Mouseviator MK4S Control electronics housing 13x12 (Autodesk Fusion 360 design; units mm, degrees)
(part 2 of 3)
sketch "Sketch2" plane through (0, 61.9879, 0) normal (0, 1, 0) x axis (-1, 0, 0)
  line L1 (-11.0351, 74.95) -> (-130.8937, 74.95)
  line L2 (-130.8937, 74.95) -> (-130.8937, 5.05)
  line L3 (-11.0351, 74.95) -> (-11.0351, 5.05)
  line L4 (-11.0351, 5.05) -> (-130.8937, 5.05)
  line L5 (-11.0351, 74.95) -> (-11.0351, 5.05)
  line L6 (-130.8937, 74.95) -> (-11.0351, 74.95)
  line L7 (-130.8937, 5.05) -> (-130.8937, 74.95)
  line L8 (-120.8937, 64.95) -> (-21.0351, 64.95)
  line L9 (-120.8937, 15.05) -> (-120.8937, 64.95)
  line L10 (-21.0351, 15.05) -> (-120.8937, 15.05)
  line L11 (-21.0351, 64.95) -> (-21.0351, 15.05)
  circle C1 centre (-125.9644, 60) radius 1.7
  circle C2 centre (-125.9644, 20) radius 1.7
  circle C3 centre (-15.9644, 20) radius 1.7
  circle C4 centre (-15.9644, 60) radius 1.7
hole "Hole1" HoleDepth 4 HoleDiameter 3.4 TipAngle 118
extrude "Extrude2" cut sketch "Sketch2" profile of L8 L10 L9 L11 no distance stored
mirror_component "MirrorComponent3"
derived_instance "DerivedInstance3"
extrude "Extrude7" add sketch "left side holes" profile of C1 L13 L14 L15 L16 along normal blind 1.45 (= "( top_cover_thickness / 2 ) - wall_clearance")
extrude "Extrude3" cut sketch "base" profile of L9 L10 L11 L12 L13 L14 L15 L16 L17 L18 L19 L20 L21 L22 L23 L24 along normal blind 1.5 (= "top_cover_thickness / 2")
extrude "Extrude2" add sketch "Sketch1" along normal blind 2.5 (= "plate_thick / 2")
extrude "Extrude4" cut sketch "Sketch1" profile of L13 L12 L15 L14 L16 L17 C2 C3 C4 C5 along normal blind 2.55 (= "( plate_thick / 2 ) + wall_clearance")
sketch "Sketch1" plane through (0, 0, 0) normal (0, 0, 1) x axis (1, 0, 0)
  line L1 (-15, -9) -> (-15, 21)
  line L2 (-7, 6) -> (-28, 6)
  line L3 (-18, 16) -> (-18, 6)
  line L4 (-18, -4) -> (-18, 6)
  line L5 (-15, 21) -> (-18, 16)
  line L6 (-15, -9) -> (-18, -4)
  line L7 (-21, -9) -> (-18, -4)
  line L8 (-18, -4) -> (-18, 6)
  line L9 (-18, 16) -> (-18, 6)
  line L10 (-21, 21) -> (-18, 16)
  line L11 (-21, -9) -> (-21, 21)
  line L12 (-15.05, 20.8195) -> (-18, 15.9028)
  line L13 (-15.05, -8.8195) -> (-15.05, 20.8195)
  line L14 (-15.05, -8.8195) -> (-18, -3.9028)
  line L15 (-20.95, -8.8195) -> (-18, -3.9028)
  line L16 (-20.95, -8.8195) -> (-20.95, 20.8195)
  line L17 (-20.95, 20.8195) -> (-18, 15.9028)
  line L18 (-16.5, -15) -> (-16.5, 22.7414)
  circle C1 centre (-16.5, 11) radius 0.75
  circle C2 centre (-16.5, 11) radius 0.7
  circle C3 centre (-16.5, 1) radius 0.7
  circle C4 centre (-19.5, 11) radius 0.7
  circle C5 centre (-19.5, 1) radius 0.7
  point P2 (-15, 21)
  point P13 (-21, 21)
  point P3 (-15, -9)
  point P10 (-21, -9)
  point P6 (-18, 6)
  point P11 (-18, 6)
  point P7 (-18, 16)
  point P12 (-18, 16)
  point P8 (-18, -4)
  point P9 (-18, -4)
  point P22 (-16.5, 11)
  vertical L1
  horizontal L2
  perpendicular L2 L3
  perpendicular L2 L4
  symmetric P2 L3 P13
  symmetric P3 L3 P10
  symmetric P6 L3 P11
  symmetric P7 L3 P12
  symmetric L3 P8 P9
  parallel L1 L18
  coincident L18 P22
  symmetric L2 C2 C3
  symmetric L4 C2 C4
  symmetric L4 C3 C5
  dimension "d49_1" distance P6 P7 = 10 (= "join_width1")
  dimension "d50_1" distance P6 P8 = 10 (= "join_width1")
  dimension "d51_1" distance P2 P3 = 30 (= "join_width2 * 2")
  dimension "d52_1" distance L1 L3 = 3 (= "join_depth")
  dimension "joiner_spacing_3" = -0.05
  dimension "d256_1" distance L9 L18 = 1.5 (= "join_depth / 2")
  dimension "d257_1" diameter C1 = 1.5 (= "join_key_d")
  dimension "d258_1" distance L2 P22 = 5 (= "join_key_distance")
extrude "Extrude1" new body sketch "Sketch1" profile of L13 L12 L15 L14 L16 L17 along normal blind 5 (= "plate_thick") named "d54_1"
extrude "Extrude4" cut sketch "Sketch1" profile of L13 L12 L15 L14 L16 L17 C2 C3 C4 C5 along normal blind 2.55 (= "( plate_thick / 2 ) + wall_clearance") named "d260_1"
sketch "Sketch1" plane through (0, 0, 0) normal (0, 0, 1) x axis (1, 0, 0)
  line L1 (-15, -9) -> (-15, 21)
  line L2 (-7, 6) -> (-28, 6)
  line L3 (-18, 16) -> (-18, 6)
  line L4 (-18, -4) -> (-18, 6)
  line L5 (-15, 21) -> (-18, 16)
  line L6 (-15, -9) -> (-18, -4)
  line L7 (-18, -4) -> (-18, 6)
  line L8 (-18, 16) -> (-18, 6)
  line L9 (-15.05, 20.8195) -> (-18, 15.9028)
  line L10 (-15.05, -8.8195) -> (-15.05, 20.8195)
  line L11 (-15.05, -8.8195) -> (-18, -3.9028)
  line L12 (-16.5, -15) -> (-16.5, 22.7414)
  circle C1 centre (-16.5, 11) radius 0.75
  circle C2 centre (-16.5, 11) radius 0.7
  circle C3 centre (-16.5, 1) radius 0.7
  point P6 (-18, 6)
  point P10 (-18, 6)
  point P7 (-18, 16)
  point P11 (-18, 16)
  point P8 (-18, -4)
  point P9 (-18, -4)
  point P17 (-16.5, 11)
  point P2 (-15, 21)
  point P3 (-15, -9)
  vertical L1
  horizontal L2
  perpendicular L2 L3
  perpendicular L2 L4
  symmetric P6 L3 P10
  symmetric P7 L3 P11
  symmetric L3 P8 P9
  parallel L1 L12
  coincident L12 P17
  symmetric L2 C2 C3
  dimension "d49_1_2" distance P6 P7 = 10 (= "join_width1")
  dimension "d50_1_2" distance P6 P8 = 10 (= "join_width1")
  dimension "d51_1_2" distance P2 P3 = 30 (= "join_width2 * 2")
  dimension "d52_1_2" distance L1 L3 = 3 (= "join_depth")
  dimension "joiner_spacing_3_2" = -0.05
  dimension "d256_1_2" distance L8 L12 = 1.5 (= "join_depth / 2")
  dimension "d257_1_2" diameter C1 = 1.5 (= "join_key_d")
  dimension "d258_1_2" distance L2 P17 = 5 (= "join_key_distance")
position "Position3"
extrude "Extrude5" new body sketch "Sketch1" profile of L3 L7 L10 L9 L11 C2 C3 along normal blind 5 (= "plate_thick")
extrude "Extrude6" cut sketch "Sketch1" profile of L3 L7 L10 L9 L11 C2 C3 along normal blind 2.55 (= "( plate_thick / 2 ) + wall_clearance")
sketch "Sketch1" plane through (0, 0, 5) normal (0, 0, 1) x axis (-1, 0, 0)
  line L1 (-128.9644, -53.9879) -> (-128.9644, -59.9879)
  line L2 (-122.9644, -53.9879) -> (-128.9644, -53.9879)
  line L3 (-122.9644, -59.9879) -> (-122.9644, -53.9879)
  line L4 (-128.9644, -59.9879) -> (-122.9644, -59.9879)
  line L5 (-12.9644, 60.0121) -> (-12.9644, 66.0121)
  line L6 (-18.9644, 60.0121) -> (-12.9644, 60.0121)
  line L7 (-18.9644, 66.0121) -> (-18.9644, 60.0121)
  line L8 (-12.9644, 66.0121) -> (-18.9644, 66.0121)
  line L9 (-60.9644, -51.9879) -> (-20.9644, -51.9879)
  line L10 (-55.9644, -54.9879) -> (-60.9644, -51.9879)
  line L11 (-85.9644, -54.9879) -> (-55.9644, -54.9879)
  line L12 (-80.9644, -51.9879) -> (-85.9644, -54.9879)
  line L13 (-120.9644, -51.9879) -> (-80.9644, -51.9879)
  line L14 (-120.9644, -6.9879) -> (-120.9644, -51.9879)
  line L15 (-123.9644, -11.9879) -> (-120.9644, -6.9879)
  line L16 (-123.9644, 18.0121) -> (-123.9644, -11.9879)
  line L17 (-120.9644, 13.0121) -> (-123.9644, 18.0121)
  line L18 (-120.9644, 58.0121) -> (-120.9644, 13.0121)
  line L19 (-80.9644, 58.0121) -> (-120.9644, 58.0121)
  line L20 (-85.9644, 61.0121) -> (-80.9644, 58.0121)
  line L21 (-55.9644, 61.0121) -> (-85.9644, 61.0121)
  line L22 (-60.9644, 58.0121) -> (-55.9644, 61.0121)
  line L23 (-20.9644, 58.0121) -> (-60.9644, 58.0121)
  line L24 (-20.9644, 13.0121) -> (-20.9644, 58.0121)
  line L25 (-17.9644, 18.0121) -> (-20.9644, 13.0121)
  line L26 (-17.9644, -11.9879) -> (-17.9644, 18.0121)
  line L27 (-20.9644, -6.9879) -> (-17.9644, -11.9879)
  line L28 (-20.9644, -51.9879) -> (-20.9644, -6.9879)
  line L29 (-12.9644, -53.9879) -> (-18.9644, -53.9879)
  line L30 (-12.9644, -59.9879) -> (-12.9644, -53.9879)
  line L31 (-18.9644, -59.9879) -> (-12.9644, -59.9879)
  line L32 (-18.9644, -53.9879) -> (-18.9644, -59.9879)
  line L33 (-128.9644, 60.0121) -> (-122.9644, 60.0121)
  line L34 (-128.9644, 66.0121) -> (-128.9644, 60.0121)
  line L35 (-122.9644, 66.0121) -> (-128.9644, 66.0121)
  line L36 (-122.9644, 60.0121) -> (-122.9644, 66.0121)
  line L37 (-10.9644, -6.9879) -> (-10.9644, -61.9879)
  line L38 (-13.9644, -11.9879) -> (-10.9644, -6.9879)
  line L39 (-13.9644, 18.0121) -> (-13.9644, -11.9879)
  line L40 (-10.9644, 13.0121) -> (-13.9644, 18.0121)
  line L41 (-10.9644, 68.0121) -> (-10.9644, 13.0121)
  line L42 (-60.9644, 68.0121) -> (-10.9644, 68.0121)
  line L43 (-55.9644, 65.0121) -> (-60.9644, 68.0121)
  line L44 (-85.9644, 65.0121) -> (-55.9644, 65.0121)
  line L45 (-80.9644, 68.0121) -> (-85.9644, 65.0121)
  line L46 (-130.9644, 68.0121) -> (-80.9644, 68.0121)
  line L47 (-130.9644, 13.0121) -> (-130.9644, 68.0121)
  line L48 (-127.9644, 18.0121) -> (-130.9644, 13.0121)
  line L49 (-127.9644, -11.9879) -> (-127.9644, 18.0121)
  line L50 (-130.9644, -6.9879) -> (-127.9644, -11.9879)
  line L51 (-130.9644, -61.9879) -> (-130.9644, -6.9879)
  line L52 (-80.9644, -61.9879) -> (-130.9644, -61.9879)
  line L53 (-85.9644, -58.9879) -> (-80.9644, -61.9879)
  line L54 (-55.9644, -58.9879) -> (-85.9644, -58.9879)
  line L55 (-60.9644, -61.9879) -> (-55.9644, -58.9879)
  line L56 (-10.9644, -61.9879) -> (-60.9644, -61.9879)
  line L57 (-130.9644, -61.9879) -> (-10.9644, -61.9879)
  line L58 (-129.9644, -60.9879) -> (-130.9644, -61.9879)
  line L59 (-121.9644, -60.9879) -> (-129.9644, -60.9879)
  line L60 (-121.9644, -59.9879) -> (-121.9644, -60.9879)
  line L61 (-19.9644, -59.9879) -> (-121.9644, -59.9879)
  line L62 (-19.9644, -60.9879) -> (-19.9644, -59.9879)
  line L63 (-11.9644, -60.9879) -> (-19.9644, -60.9879)
  line L64 (-10.9644, -61.9879) -> (-11.9644, -60.9879)
  line L65 (-129.9437, -61.0379) -> (-130.8937, -61.9879)
  line L66 (-121.9144, -61.0379) -> (-129.9437, -61.0379)
  line L67 (-121.9144, -60.0379) -> (-121.9144, -61.0379)
  line L68 (-20.0144, -60.0379) -> (-121.9144, -60.0379)
  line L69 (-20.0144, -61.0379) -> (-20.0144, -60.0379)
  line L70 (-11.9851, -61.0379) -> (-20.0144, -61.0379)
  line L71 (-11.0351, -61.9879) -> (-11.9851, -61.0379)
  circle C1 centre (-24.4644, 61.5121) radius 1.7
  circle C2 centre (-123.9644, 54.5121) radius 1.7
  circle C3 centre (-117.4644, -55.4879) radius 1.7
  circle C4 centre (-17.4644, -48.4879) radius 1.7
  circle C5 centre (-24.4644, -55.4879) radius 1.7
  circle C6 centre (-123.9644, -48.4879) radius 1.7
  circle C7 centre (-117.4644, 61.5121) radius 1.7
  circle C8 centre (-17.4644, 54.5121) radius 1.7
  point P46 (-10.9644, -61.9879)
  point P74 (-10.9644, -61.9879)
  point P61 (-130.9644, -61.9879)
  point P76 (-130.9644, -61.9879)
  point P68 (-129.9644, -60.9879)
  point P77 (-129.9644, -60.9879)
  point P69 (-121.9644, -60.9879)
  point P78 (-121.9644, -60.9879)
  point P70 (-121.9644, -59.9879)
  point P79 (-121.9644, -59.9879)
  point P71 (-19.9644, -59.9879)
  point P80 (-19.9644, -59.9879)
  point P72 (-19.9644, -60.9879)
  point P81 (-19.9644, -60.9879)
  point P73 (-11.9644, -60.9879)
  point P82 (-11.9644, -60.9879)
  point P89 (-11.0351, -61.9879)
  point P90 (-130.8937, -61.9879)
  point P75 (-130.9644, -61.9879)
  coincident P46 P74
  coincident P61 P76
  coincident P68 P77
  coincident P69 P78
  coincident P70 P79
  coincident P71 P80
  coincident P72 P81
  coincident P73 P82
  coincident L56 P89
  coincident L52 P90
  dimension "d228_1" distance L57 L70 = 0.95 (= "side_wall_thick1")
  dimension "d229_1" distance L57 L68 = 1.95 (= "side_wall_thick2")
  dimension "d230_1" distance L57 L66 = 0.95 (= "side_wall_thick1")
  dimension "d231_1" distance P74 P75 = 120 (= "plate_height")
  dimension "d232_1" distance L64 L71 = 0.05 (= "wall_clearance")
  dimension "d233_1" distance L58 L65 = 0.05 (= "wall_clearance")
  dimension "d234_1" angle L57 L58 = 45 (= "wall_rorner_angle")
  dimension "d235_1" distance P74 L69 = 9.05 (= "side_wall_col_length")
  dimension "d244_1" distance P75 L67 = 9.05 (= "side_wall_col_length")
extrude "Extrude1" new body sketch "Sketch1" profile of L52 L53 L55 L56 blind 69.9 (= "column_height - ( 2 * wall_clearance )") named "d217_1" from offset 0.05 (= "wall_clearance") named "d216_1"
sketch "Sketch2" plane through (0, 61.9879, 0) normal (0, 1, 0) x axis (-1, 0, 0)
  line L1 (-11.0351, 74.95) -> (-130.8937, 74.95)
  line L2 (-130.8937, 74.95) -> (-130.8937, 5.05)
  line L3 (-11.0351, 74.95) -> (-11.0351, 5.05)
  line L4 (-11.0351, 5.05) -> (-130.8937, 5.05)
  line L5 (-11.0351, 74.95) -> (-11.0351, 5.05)
  line L6 (-130.8937, 74.95) -> (-11.0351, 74.95)
  line L7 (-130.8937, 5.05) -> (-130.8937, 74.95)
  line L8 (-120.8937, 64.95) -> (-21.0351, 64.95)
  line L9 (-120.8937, 15.05) -> (-120.8937, 64.95)
  line L10 (-21.0351, 15.05) -> (-120.8937, 15.05)
  line L11 (-21.0351, 64.95) -> (-21.0351, 15.05)
  circle C1 centre (-125.9644, 60) radius 1.7
  circle C2 centre (-125.9644, 20) radius 1.7
  circle C3 centre (-15.9644, 20) radius 1.7
  circle C4 centre (-15.9644, 60) radius 1.7
hole "Hole1" HoleDepth 4 named "d220_1" HoleDiameter 3.4 named "d221_1" TipAngle 118 named "d222_1"
sketch "Sketch3" plane through (0, 61.9879, 0) normal (0, 1, 0) x axis (-1, 0, 0)
  line L1 (-37.0714, 20.7092) -> (-37, 5)
  line L2 (-27.0715, 20.7546) -> (-27, 5)
  line L3 (-130.8937, 5.05) -> (-130.8937, 74.95)
  line L4 (-11.0351, 5.05) -> (-130.8937, 5.05)
  line L5 (-11.0351, 74.95) -> (-11.0351, 5.05)
  line L6 (-130.8937, 74.95) -> (-11.0351, 74.95)
  arc A1 centre (-32.0715, 20.7319) radius 5 clockwise from (-37.0714, 20.7092) to (-27.0715, 20.7546)
  tangent L1 A1
  tangent L2 A1
  dimension "d338" diameter A1 = 10
extrude "Extrude3" cut sketch "Sketch3" profile of A1 L1 L2 L4 no distance stored
sketch "Sketch1" plane through (0, 0, 5) normal (0, 0, 1) x axis (-1, 0, 0)
  line L1 (-128.9644, -53.9879) -> (-128.9644, -59.9879)
  line L2 (-122.9644, -53.9879) -> (-128.9644, -53.9879)
  line L3 (-122.9644, -59.9879) -> (-122.9644, -53.9879)
  line L4 (-128.9644, -59.9879) -> (-122.9644, -59.9879)
  line L5 (-12.9644, 60.0121) -> (-12.9644, 66.0121)
  line L6 (-18.9644, 60.0121) -> (-12.9644, 60.0121)
  line L7 (-18.9644, 66.0121) -> (-18.9644, 60.0121)
  line L8 (-12.9644, 66.0121) -> (-18.9644, 66.0121)
  line L9 (-60.9644, -51.9879) -> (-20.9644, -51.9879)
  line L10 (-55.9644, -54.9879) -> (-60.9644, -51.9879)
  line L11 (-85.9644, -54.9879) -> (-55.9644, -54.9879)
  line L12 (-80.9644, -51.9879) -> (-85.9644, -54.9879)
  line L13 (-120.9644, -51.9879) -> (-80.9644, -51.9879)
  line L14 (-120.9644, -6.9879) -> (-120.9644, -51.9879)
  line L15 (-123.9644, -11.9879) -> (-120.9644, -6.9879)
  line L16 (-123.9644, 18.0121) -> (-123.9644, -11.9879)
  line L17 (-120.9644, 13.0121) -> (-123.9644, 18.0121)
  line L18 (-120.9644, 58.0121) -> (-120.9644, 13.0121)
  line L19 (-80.9644, 58.0121) -> (-120.9644, 58.0121)
  line L20 (-85.9644, 61.0121) -> (-80.9644, 58.0121)
  line L21 (-55.9644, 61.0121) -> (-85.9644, 61.0121)
  line L22 (-60.9644, 58.0121) -> (-55.9644, 61.0121)
  line L23 (-20.9644, 58.0121) -> (-60.9644, 58.0121)
  line L24 (-20.9644, 13.0121) -> (-20.9644, 58.0121)
  line L25 (-17.9644, 18.0121) -> (-20.9644, 13.0121)
  line L26 (-17.9644, -11.9879) -> (-17.9644, 18.0121)
  line L27 (-20.9644, -6.9879) -> (-17.9644, -11.9879)
  line L28 (-20.9644, -51.9879) -> (-20.9644, -6.9879)
  line L29 (-12.9644, -53.9879) -> (-18.9644, -53.9879)
  line L30 (-12.9644, -59.9879) -> (-12.9644, -53.9879)
  line L31 (-18.9644, -59.9879) -> (-12.9644, -59.9879)
  line L32 (-18.9644, -53.9879) -> (-18.9644, -59.9879)
  line L33 (-128.9644, 60.0121) -> (-122.9644, 60.0121)
  line L34 (-128.9644, 66.0121) -> (-128.9644, 60.0121)
  line L35 (-122.9644, 66.0121) -> (-128.9644, 66.0121)
  line L36 (-122.9644, 60.0121) -> (-122.9644, 66.0121)
  line L37 (-10.9644, -6.9879) -> (-10.9644, -61.9879)
  line L38 (-13.9644, -11.9879) -> (-10.9644, -6.9879)
  line L39 (-13.9644, 18.0121) -> (-13.9644, -11.9879)
  line L40 (-10.9644, 13.0121) -> (-13.9644, 18.0121)
  line L41 (-10.9644, 68.0121) -> (-10.9644, 13.0121)
  line L42 (-60.9644, 68.0121) -> (-10.9644, 68.0121)
  line L43 (-55.9644, 65.0121) -> (-60.9644, 68.0121)
  line L44 (-85.9644, 65.0121) -> (-55.9644, 65.0121)
  line L45 (-80.9644, 68.0121) -> (-85.9644, 65.0121)
  line L46 (-130.9644, 68.0121) -> (-80.9644, 68.0121)
  line L47 (-130.9644, 13.0121) -> (-130.9644, 68.0121)
  line L48 (-127.9644, 18.0121) -> (-130.9644, 13.0121)
  line L49 (-127.9644, -11.9879) -> (-127.9644, 18.0121)
  line L50 (-130.9644, -6.9879) -> (-127.9644, -11.9879)
  line L51 (-130.9644, -61.9879) -> (-130.9644, -6.9879)
  line L52 (-80.9644, -61.9879) -> (-130.9644, -61.9879)
  line L53 (-85.9644, -58.9879) -> (-80.9644, -61.9879)
  line L54 (-55.9644, -58.9879) -> (-85.9644, -58.9879)
  line L55 (-60.9644, -61.9879) -> (-55.9644, -58.9879)
  line L56 (-10.9644, -61.9879) -> (-60.9644, -61.9879)
  line L57 (-130.9644, -61.9879) -> (-10.9644, -61.9879)
  line L58 (-129.9644, -60.9879) -> (-130.9644, -61.9879)
  line L59 (-121.9644, -60.9879) -> (-129.9644, -60.9879)
  line L60 (-121.9644, -59.9879) -> (-121.9644, -60.9879)
  line L61 (-19.9644, -59.9879) -> (-121.9644, -59.9879)
  line L62 (-19.9644, -60.9879) -> (-19.9644, -59.9879)
  line L63 (-11.9644, -60.9879) -> (-19.9644, -60.9879)
  line L64 (-10.9644, -61.9879) -> (-11.9644, -60.9879)
  line L65 (-129.9437, -61.0379) -> (-130.8937, -61.9879)
  line L66 (-121.9144, -61.0379) -> (-129.9437, -61.0379)
  line L67 (-121.9144, -60.0379) -> (-121.9144, -61.0379)
  line L68 (-20.0144, -60.0379) -> (-121.9144, -60.0379)
  line L69 (-20.0144, -61.0379) -> (-20.0144, -60.0379)
  line L70 (-11.9851, -61.0379) -> (-20.0144, -61.0379)
  line L71 (-11.0351, -61.9879) -> (-11.9851, -61.0379)
  circle C1 centre (-24.4644, 61.5121) radius 1.7
  circle C2 centre (-123.9644, 54.5121) radius 1.7
  circle C3 centre (-117.4644, -55.4879) radius 1.7
  circle C4 centre (-17.4644, -48.4879) radius 1.7
  circle C5 centre (-24.4644, -55.4879) radius 1.7
  circle C6 centre (-123.9644, -48.4879) radius 1.7
  circle C7 centre (-117.4644, 61.5121) radius 1.7
  circle C8 centre (-17.4644, 54.5121) radius 1.7
  point P46 (-10.9644, -61.9879)
  point P74 (-10.9644, -61.9879)
  point P61 (-130.9644, -61.9879)
  point P76 (-130.9644, -61.9879)
  point P68 (-129.9644, -60.9879)
  point P77 (-129.9644, -60.9879)
  point P69 (-121.9644, -60.9879)
  point P78 (-121.9644, -60.9879)
  point P70 (-121.9644, -59.9879)
  point P79 (-121.9644, -59.9879)
  point P71 (-19.9644, -59.9879)
  point P80 (-19.9644, -59.9879)
  point P72 (-19.9644, -60.9879)
  point P81 (-19.9644, -60.9879)
  point P73 (-11.9644, -60.9879)
  point P82 (-11.9644, -60.9879)
  point P89 (-11.0351, -61.9879)
  point P90 (-130.8937, -61.9879)
  point P75 (-130.9644, -61.9879)
  coincident P46 P74
  coincident P61 P76
  coincident P68 P77
  coincident P69 P78
  coincident P70 P79
  coincident P71 P80
  coincident P72 P81
  coincident P73 P82
  coincident L56 P89
  coincident L52 P90
  dimension "d228_2" distance L57 L70 = 0.95 (= "side_wall_thick1")
  dimension "d229_2" distance L57 L68 = 1.95 (= "side_wall_thick2")
  dimension "d230_2" distance L57 L66 = 0.95 (= "side_wall_thick1")
  dimension "d231_2" distance P74 P75 = 120 (= "plate_height")
  dimension "d232_2" distance L64 L71 = 0.05 (= "wall_clearance")
  dimension "d233_2" distance L58 L65 = 0.05 (= "wall_clearance")
  dimension "d234_2" angle L57 L58 = 45 (= "wall_rorner_angle")
  dimension "d235_2" distance P74 L69 = 9.05 (= "side_wall_col_length")
  dimension "d244_2" distance P75 L67 = 9.05 (= "side_wall_col_length")
extrude "Extrude1" new body sketch "Sketch1" profile of L52 L53 L55 L56 blind 69.9 (= "column_height - ( 2 * wall_clearance )") named "d217_2" from offset 0.05 (= "wall_clearance") named "d216_2"
sketch "Sketch2" plane through (0, 61.9879, 0) normal (0, 1, 0) x axis (-1, 0, 0)
  line L1 (-11.0351, 74.95) -> (-130.8937, 74.95)
  line L2 (-130.8937, 74.95) -> (-130.8937, 5.05)
  line L3 (-11.0351, 74.95) -> (-11.0351, 5.05)
  line L4 (-11.0351, 5.05) -> (-130.8937, 5.05)
  line L5 (-11.0351, 74.95) -> (-11.0351, 5.05)
  line L6 (-130.8937, 74.95) -> (-11.0351, 74.95)
  line L7 (-130.8937, 5.05) -> (-130.8937, 74.95)
  line L8 (-120.8937, 64.95) -> (-21.0351, 64.95)
  line L9 (-120.8937, 15.05) -> (-120.8937, 64.95)
  line L10 (-21.0351, 15.05) -> (-120.8937, 15.05)
  line L11 (-21.0351, 64.95) -> (-21.0351, 15.05)
  circle C1 centre (-125.9644, 60) radius 1.7
  circle C2 centre (-125.9644, 20) radius 1.7
  circle C3 centre (-15.9644, 20) radius 1.7
  circle C4 centre (-15.9644, 60) radius 1.7
hole "Hole1" HoleDepth 4 named "d220_2" HoleDiameter 3.4 named "d221_2" TipAngle 118 named "d222_2"
sketch "wall_base" plane through (0, 0, 5) normal (0, 0, 1) x axis (-1, 0, 0)
  line L1 (-128.9644, -53.9879) -> (-128.9644, -59.9879)
  line L2 (-122.9644, -53.9879) -> (-128.9644, -53.9879)
  line L3 (-122.9644, -59.9879) -> (-122.9644, -53.9879)
  line L4 (-128.9644, -59.9879) -> (-122.9644, -59.9879)
  line L5 (-12.9644, 60.0121) -> (-12.9644, 66.0121)
  line L6 (-18.9644, 60.0121) -> (-12.9644, 60.0121)
  line L7 (-18.9644, 66.0121) -> (-18.9644, 60.0121)
  line L8 (-12.9644, 66.0121) -> (-18.9644, 66.0121)
  line L9 (-60.9644, -51.9879) -> (-20.9644, -51.9879)
  line L10 (-55.9644, -54.9879) -> (-60.9644, -51.9879)
  line L11 (-85.9644, -54.9879) -> (-55.9644, -54.9879)
  line L12 (-80.9644, -51.9879) -> (-85.9644, -54.9879)
  line L13 (-120.9644, -51.9879) -> (-80.9644, -51.9879)
  line L14 (-120.9644, -6.9879) -> (-120.9644, -51.9879)
  line L15 (-123.9644, -11.9879) -> (-120.9644, -6.9879)
  line L16 (-123.9644, 18.0121) -> (-123.9644, -11.9879)
  line L17 (-120.9644, 13.0121) -> (-123.9644, 18.0121)
  line L18 (-120.9644, 58.0121) -> (-120.9644, 13.0121)
  line L19 (-80.9644, 58.0121) -> (-120.9644, 58.0121)
  line L20 (-85.9644, 61.0121) -> (-80.9644, 58.0121)
  line L21 (-55.9644, 61.0121) -> (-85.9644, 61.0121)
  line L22 (-60.9644, 58.0121) -> (-55.9644, 61.0121)
  line L23 (-20.9644, 58.0121) -> (-60.9644, 58.0121)
  line L24 (-20.9644, 13.0121) -> (-20.9644, 58.0121)
  line L25 (-17.9644, 18.0121) -> (-20.9644, 13.0121)
  line L26 (-17.9644, -11.9879) -> (-17.9644, 18.0121)
  line L27 (-20.9644, -6.9879) -> (-17.9644, -11.9879)
  line L28 (-20.9644, -51.9879) -> (-20.9644, -6.9879)
  line L29 (-12.9644, -53.9879) -> (-18.9644, -53.9879)
  line L30 (-12.9644, -59.9879) -> (-12.9644, -53.9879)
  line L31 (-18.9644, -59.9879) -> (-12.9644, -59.9879)
  line L32 (-18.9644, -53.9879) -> (-18.9644, -59.9879)
  line L33 (-128.9644, 60.0121) -> (-122.9644, 60.0121)
  line L34 (-128.9644, 66.0121) -> (-128.9644, 60.0121)
  line L35 (-122.9644, 66.0121) -> (-128.9644, 66.0121)
  line L36 (-122.9644, 60.0121) -> (-122.9644, 66.0121)
  line L37 (-10.9644, -6.9879) -> (-10.9644, -61.9879)
  line L38 (-13.9644, -11.9879) -> (-10.9644, -6.9879)
  line L39 (-13.9644, 18.0121) -> (-13.9644, -11.9879)
  line L40 (-10.9644, 13.0121) -> (-13.9644, 18.0121)
  line L41 (-10.9644, 68.0121) -> (-10.9644, 13.0121)
  line L42 (-60.9644, 68.0121) -> (-10.9644, 68.0121)
  line L43 (-55.9644, 65.0121) -> (-60.9644, 68.0121)
  line L44 (-85.9644, 65.0121) -> (-55.9644, 65.0121)
  line L45 (-80.9644, 68.0121) -> (-85.9644, 65.0121)
  line L46 (-130.9644, 68.0121) -> (-80.9644, 68.0121)
  line L47 (-130.9644, 13.0121) -> (-130.9644, 68.0121)
  line L48 (-127.9644, 18.0121) -> (-130.9644, 13.0121)
  line L49 (-127.9644, -11.9879) -> (-127.9644, 18.0121)
  line L50 (-130.9644, -6.9879) -> (-127.9644, -11.9879)
  line L51 (-130.9644, -61.9879) -> (-130.9644, -6.9879)
  line L52 (-80.9644, -61.9879) -> (-130.9644, -61.9879)
  line L53 (-85.9644, -58.9879) -> (-80.9644, -61.9879)
  line L54 (-55.9644, -58.9879) -> (-85.9644, -58.9879)
  line L55 (-60.9644, -61.9879) -> (-55.9644, -58.9879)
  line L56 (-10.9644, -61.9879) -> (-60.9644, -61.9879)
  line L57 (-130.9644, -61.9879) -> (-130.9644, 68.0121)
  line L58 (-130.9644, -61.9172) -> (-130.0144, -60.9672)
  line L59 (-130.0144, -52.9379) -> (-130.0144, -60.9672)
  line L60 (-129.0144, -52.9379) -> (-130.0144, -52.9379)
  line L61 (-129.0144, 58.9451) -> (-129.0144, -52.9379)
  line L62 (-130.0144, 58.9621) -> (-129.0144, 58.9451)
  line L63 (-130.0144, 66.9914) -> (-130.0144, 58.9621)
  line L64 (-130.9644, 67.9414) -> (-130.0144, 66.9914)
  line L65 (-129.9644, -52.9879) -> (-129.9644, -60.9879)
  line L66 (-128.9644, -52.9879) -> (-129.9644, -52.9879)
  line L67 (-128.9644, 58.9942) -> (-128.9644, -52.9879)
  line L68 (-129.9644, 59.0113) -> (-128.9644, 58.9942)
  line L69 (-129.9644, 67.0121) -> (-129.9644, 59.0113)
  line L70 (-130.9644, -61.9879) -> (-129.9644, -60.9879)
  line L71 (-130.9644, 68.0121) -> (-129.9644, 67.0121)
  circle C1 centre (-24.4644, 61.5121) radius 1.7
  circle C2 centre (-123.9644, 54.5121) radius 1.7
  circle C3 centre (-117.4644, -55.4879) radius 1.7
  circle C4 centre (-17.4644, -48.4879) radius 1.7
  circle C5 centre (-24.4644, -55.4879) radius 1.7
  circle C6 centre (-123.9644, -48.4879) radius 1.7
  circle C7 centre (-117.4644, 61.5121) radius 1.7
  circle C8 centre (-17.4644, 54.5121) radius 1.7
  point P69 (-130.9644, 68.0121)
  point P74 (-130.9644, 68.0121)
  point P68 (-130.9644, -61.9879)
  point P75 (-130.9644, -61.9879)
  point P82 (-130.9644, 67.9414)
  point P83 (-130.9644, -61.9172)
  point P90 (-130.9644, -61.9879)
  point P91 (-130.9644, 68.0121)
  point P77 (-130.0144, -52.9379)
  point P80 (-130.0144, 58.9621)
  coincident P69 P74
  coincident P68 P75
  coincident L47 P82
  coincident L51 P83
  coincident P68 P90
  parallel L58 L70
  coincident P69 P91
  dimension "d147_1" distance L57 L63 = 0.95 (= "side_wall_thick1")
  dimension "d148_1" distance L57 L61 = 1.95 (= "side_wall_thick2")
  dimension "d151_1" distance L57 L59 = 0.95 (= "side_wall_thick1")
  dimension "d157_1" distance L64 L71 = 0.05 (= "wall_clearance")
  dimension "d158_1" distance L58 L70 = 0.05 (= "wall_clearance")
  dimension "wall_rorner_angle_1" angle L46 L71 = 45
  dimension "d165_1" angle L52 L70 = 45 (= "wall_rorner_angle_1")
  dimension "d170_1" distance P75 P77 = 9.05
  dimension "d175_1" distance P74 P80 = 9.05 (= "side_wall_col_length")
extrude "Extrude1" new body sketch "wall_base" profile of L47 L48 L50 L51 L57 L58 L59 L62 L61 L60 L63 L64 blind 69.9 (= "column_height - ( 2 * wall_clearance )") named "d128_1" from offset 0.05 (= "wall_clearance") named "d127_1" bodies "side cover"
sketch "Sketch3" plane through (130.9644, 0, 0) normal (1, 0, 0) x axis (0, 1, 0)
  line L1 (61.9172, 5.05) -> (-67.9414, 5.05)
  line L2 (61.9172, 74.95) -> (61.9172, 5.05)
  line L3 (-67.9414, 74.95) -> (61.9172, 74.95)
  line L4 (-67.9414, 5.05) -> (-67.9414, 74.95)
  line L5 (61.9172, 74.95) -> (-67.9414, 74.95)
  line L6 (61.9172, 74.95) -> (61.9172, 5.05)
  line L7 (61.9172, 5.05) -> (-67.9414, 5.05)
  line L8 (-67.9414, 74.95) -> (-67.9414, 5.05)
  line L9 (-57.9414, 64.95) -> (51.9172, 64.95)
  line L10 (-57.9414, 15.05) -> (-57.9414, 64.95)
  line L11 (51.9172, 15.05) -> (-57.9414, 15.05)
  line L12 (51.9172, 64.95) -> (51.9172, 15.05)
  circle C1 centre (-62.995, 60) radius 1.7
  circle C2 centre (-62.995, 20) radius 1.7
  circle C3 centre (56.9879, 60) radius 1.7
  circle C4 centre (56.9879, 20) radius 1.7
hole "Hole1" HoleDepth 4 named "d134_1" HoleDiameter 3.4 named "d135_1" TipAngle 118 named "d136_1"
position "Position7"
extrude "Extrude3" cut sketch "Sketch3" profile of L9 L10 L12 L11 no distance stored
base_mesh_feature "Base Mesh Feature"
convert_mesh "Convert Mesh" bodies "Base plate 13x12 insert - PSU holder"
component_from_bodies "Body->Comp"
delete_face "DeleteFace1"
delete_face "DeleteFace2"
delete_face "DeleteFace3"
delete_face "DeleteFace4"
delete_face "DeleteFace5"
delete_face "DeleteFace6"
delete_face "DeleteFace7"
delete_face "DeleteFace8"
delete_face "DeleteFace9"
delete_face "DeleteFace10"
delete_face "DeleteFace11"
delete_face "DeleteFace12"
sketch "Sketch1" plane through (0, 0, 0) normal (0, 0, 1) x axis (1, 0, 0)
  line L1 (-15, -9) -> (-15, 21)
  line L2 (-7, 6) -> (-28, 6)
  line L3 (-18, 16) -> (-18, 6)
  line L4 (-18, -4) -> (-18, 6)
  line L5 (-15, 21) -> (-18, 16)
  line L6 (-15, -9) -> (-18, -4)
  line L7 (-18, -4) -> (-18, 6)
  line L8 (-18, 16) -> (-18, 6)
  line L9 (-15.05, 20.8195) -> (-18, 15.9028)
  line L10 (-15.05, -8.8195) -> (-15.05, 20.8195)
  line L11 (-15.05, -8.8195) -> (-18, -3.9028)
  line L12 (-16.5, -15) -> (-16.5, 22.7414)
  circle C1 centre (-16.5, 11) radius 0.75
  circle C2 centre (-16.5, 11) radius 0.7
  circle C3 centre (-16.5, 1) radius 0.7
  point P6 (-18, 6)
  point P10 (-18, 6)
  point P7 (-18, 16)
  point P11 (-18, 16)
  point P8 (-18, -4)
  point P9 (-18, -4)
  point P17 (-16.5, 11)
  point P2 (-15, 21)
  point P3 (-15, -9)
  vertical L1
  horizontal L2
  perpendicular L2 L3
  perpendicular L2 L4
  symmetric P6 L3 P10
  symmetric P7 L3 P11
  symmetric L3 P8 P9
  parallel L1 L12
  coincident L12 P17
  symmetric L2 C2 C3
  dimension "d49_1_2_1" distance P6 P7 = 10 (= "join_width1")
  dimension "d50_1_2_1" distance P6 P8 = 10 (= "join_width1")
  dimension "d51_1_2_1" distance P2 P3 = 30 (= "join_width2 * 2")
  dimension "d52_1_2_1" distance L1 L3 = 3 (= "join_depth")
  dimension "joiner_spacing_3_2_1" = -0.05
  dimension "d256_1_2_1" distance L8 L12 = 1.5 (= "join_depth / 2")
  dimension "d257_1_2_1" diameter C1 = 1.5 (= "join_key_d")
  dimension "d258_1_2_1" distance L2 P17 = 5 (= "join_key_distance")
position "Position4"
extrude "Extrude5" new body sketch "Sketch1" profile of L3 L7 L10 L9 L11 C2 C3 along normal blind 3 (= "top_cover_thickness") named "d262_1"
extrude "Extrude6" cut sketch "Sketch1" profile of L3 L7 L10 L9 L11 C2 C3 along normal blind 1.55 (= "( top_cover_thickness / 2 ) + wall_clearance") named "d264_1"
sketch "Sketch1" plane through (0, 0, 0) normal (0, 0, 1) x axis (1, 0, 0)
  line L1 (-15, -9) -> (-15, 21)
  line L2 (-7, 6) -> (-28, 6)
  line L3 (-18, 16) -> (-18, 6)
  line L4 (-18, -4) -> (-18, 6)
  line L5 (-15, 21) -> (-18, 16)
  line L6 (-15, -9) -> (-18, -4)
  line L7 (-21, -9) -> (-18, -4)
  line L8 (-18, -4) -> (-18, 6)
  line L9 (-18, 16) -> (-18, 6)
  line L10 (-21, 21) -> (-18, 16)
  line L11 (-21, -9) -> (-21, 21)
  line L12 (-15.05, 20.8195) -> (-18, 15.9028)
  line L13 (-15.05, -8.8195) -> (-15.05, 20.8195)
  line L14 (-15.05, -8.8195) -> (-18, -3.9028)
  line L15 (-20.95, -8.8195) -> (-18, -3.9028)
  line L16 (-20.95, -8.8195) -> (-20.95, 20.8195)
  line L17 (-20.95, 20.8195) -> (-18, 15.9028)
  line L18 (-16.5, -15) -> (-16.5, 22.7414)
  circle C1 centre (-16.5, 11) radius 0.75
  circle C2 centre (-16.5, 11) radius 0.7
  circle C3 centre (-16.5, 1) radius 0.7
  circle C4 centre (-19.5, 11) radius 0.7
  circle C5 centre (-19.5, 1) radius 0.7
  point P2 (-15, 21)
  point P13 (-21, 21)
  point P3 (-15, -9)
  point P10 (-21, -9)
  point P6 (-18, 6)
  point P11 (-18, 6)
  point P7 (-18, 16)
  point P12 (-18, 16)
  point P8 (-18, -4)
  point P9 (-18, -4)
  point P22 (-16.5, 11)
  vertical L1
  horizontal L2
  perpendicular L2 L3
  perpendicular L2 L4
  symmetric P2 L3 P13
  symmetric P3 L3 P10
  symmetric P6 L3 P11
  symmetric P7 L3 P12
  symmetric L3 P8 P9
  parallel L1 L18
  coincident L18 P22
  symmetric L2 C2 C3
  symmetric L4 C2 C4
  symmetric L4 C3 C5
  dimension "d49_1_1" distance P6 P7 = 10 (= "join_width1")
  dimension "d50_1_1" distance P6 P8 = 10 (= "join_width1")
  dimension "d51_1_1" distance P2 P3 = 30 (= "join_width2 * 2")
  dimension "d52_1_1" distance L1 L3 = 3 (= "join_depth")
  dimension "joiner_spacing_3_3" = -0.05
  dimension "d256_1_1" distance L9 L18 = 1.5 (= "join_depth / 2")
  dimension "d257_1_1" diameter C1 = 1.5 (= "join_key_d")
  dimension "d258_1_1" distance L2 P22 = 5 (= "join_key_distance")
extrude "Extrude1" new body sketch "Sketch1" profile of L13 L12 L15 L14 L16 L17 C2 C3 C4 C5 along normal blind 3 (= "top_cover_thickness") named "d54_1_1"
extrude "Extrude4" cut sketch "Sketch1" profile of L13 L12 L15 L14 L16 L17 C2 C3 C4 C5 along normal blind 1.55 (= "( top_cover_thickness / 2 ) + wall_clearance") named "d260_1_1"
position "Position5"
sketch "base" plane through (0, 0, 0) normal (0, 0, 1) x axis (1, 0, 0)
  line L1 (12.9644, 53.9879) -> (18.9644, 53.9879)
  line L2 (12.9644, 59.9879) -> (12.9644, 53.9879)
  line L3 (18.9644, 59.9879) -> (12.9644, 59.9879)
  line L4 (18.9644, 53.9879) -> (18.9644, 59.9879)
  line L5 (13.0144, 54.0379) -> (18.9144, 54.0379)
  line L6 (13.0144, 59.9379) -> (13.0144, 54.0379)
  line L7 (18.9144, 59.9379) -> (13.0144, 59.9379)
  line L8 (18.9144, 54.0379) -> (18.9144, 59.9379)
  line L9 (11.9644, 52.9879) -> (19.9644, 52.9879)
  line L10 (11.9644, 60.9879) -> (11.9644, 52.9879)
  line L11 (19.9644, 60.9879) -> (11.9644, 60.9879)
  line L12 (19.9644, 52.9879) -> (19.9644, 60.9879)
  dimension "d67_1" = 0.05
  dimension "d68_1" = -1
extrude "Extrude2" new body sketch "base" profile of L1 L2 L3 L4 L9 L10 L11 L12 blind 70 (= "column_height") named "d73_1" from offset 5 (= "plate_thick") named "d72_1"
extrude "Extrude3" add sketch "Sketch1" profile of L36 L35 L38 L37 along normal blind 75 (= "plate_thick + column_height") named "d75_1"
sketch "supports bottom" plane through (0, 0, 5) normal (0, 0, 1) x axis (-1, 0, 0)
  line L1 (-128.9644, -53.9879) -> (-128.9644, -59.9879)
  line L2 (-122.9644, -53.9879) -> (-128.9644, -53.9879)
  line L3 (-122.9644, -59.9879) -> (-122.9644, -53.9879)
  line L4 (-128.9644, -59.9879) -> (-122.9644, -59.9879)
  line L5 (-12.9644, 60.0121) -> (-12.9644, 66.0121)
  line L6 (-18.9644, 60.0121) -> (-12.9644, 60.0121)
  line L7 (-18.9644, 66.0121) -> (-18.9644, 60.0121)
  line L8 (-12.9644, 66.0121) -> (-18.9644, 66.0121)
  line L9 (-60.9644, -51.9879) -> (-20.9644, -51.9879)
  line L10 (-55.9644, -54.9879) -> (-60.9644, -51.9879)
  line L11 (-85.9644, -54.9879) -> (-55.9644, -54.9879)
  line L12 (-80.9644, -51.9879) -> (-85.9644, -54.9879)
  line L13 (-120.9644, -51.9879) -> (-80.9644, -51.9879)
  line L14 (-120.9644, -6.9879) -> (-120.9644, -51.9879)
  line L15 (-123.9644, -11.9879) -> (-120.9644, -6.9879)
  line L16 (-123.9644, 18.0121) -> (-123.9644, -11.9879)
  line L17 (-120.9644, 13.0121) -> (-123.9644, 18.0121)
  line L18 (-120.9644, 58.0121) -> (-120.9644, 13.0121)
  line L19 (-80.9644, 58.0121) -> (-120.9644, 58.0121)
  line L20 (-85.9644, 61.0121) -> (-80.9644, 58.0121)
  line L21 (-55.9644, 61.0121) -> (-85.9644, 61.0121)
  line L22 (-60.9644, 58.0121) -> (-55.9644, 61.0121)
  line L23 (-20.9644, 58.0121) -> (-60.9644, 58.0121)
  line L24 (-20.9644, 13.0121) -> (-20.9644, 58.0121)
  line L25 (-17.9644, 18.0121) -> (-20.9644, 13.0121)
  line L26 (-17.9644, -11.9879) -> (-17.9644, 18.0121)
  line L27 (-20.9644, -6.9879) -> (-17.9644, -11.9879)
  line L28 (-20.9644, -51.9879) -> (-20.9644, -6.9879)
  line L29 (-12.9644, -53.9879) -> (-18.9644, -53.9879)
  line L30 (-12.9644, -59.9879) -> (-12.9644, -53.9879)
  line L31 (-18.9644, -59.9879) -> (-12.9644, -59.9879)
  line L32 (-18.9644, -53.9879) -> (-18.9644, -59.9879)
  line L33 (-128.9644, 60.0121) -> (-122.9644, 60.0121)
  line L34 (-128.9644, 66.0121) -> (-128.9644, 60.0121)
  line L35 (-122.9644, 66.0121) -> (-128.9644, 66.0121)
  line L36 (-122.9644, 60.0121) -> (-122.9644, 66.0121)
  line L37 (-10.9644, -6.9879) -> (-10.9644, -61.9879)
  line L38 (-13.9644, -11.9879) -> (-10.9644, -6.9879)
  line L39 (-13.9644, 18.0121) -> (-13.9644, -11.9879)
  line L40 (-10.9644, 13.0121) -> (-13.9644, 18.0121)
  line L41 (-10.9644, 68.0121) -> (-10.9644, 13.0121)
  line L42 (-60.9644, 68.0121) -> (-10.9644, 68.0121)
  line L43 (-55.9644, 65.0121) -> (-60.9644, 68.0121)
  line L44 (-85.9644, 65.0121) -> (-55.9644, 65.0121)
  line L45 (-80.9644, 68.0121) -> (-85.9644, 65.0121)
  line L46 (-130.9644, 68.0121) -> (-80.9644, 68.0121)
  line L47 (-130.9644, 13.0121) -> (-130.9644, 68.0121)
  line L48 (-127.9644, 18.0121) -> (-130.9644, 13.0121)
  line L49 (-127.9644, -11.9879) -> (-127.9644, 18.0121)
  line L50 (-130.9644, -6.9879) -> (-127.9644, -11.9879)
  line L51 (-130.9644, -61.9879) -> (-130.9644, -6.9879)
  line L52 (-80.9644, -61.9879) -> (-130.9644, -61.9879)
  line L53 (-85.9644, -58.9879) -> (-80.9644, -61.9879)
  line L54 (-55.9644, -58.9879) -> (-85.9644, -58.9879)
  line L55 (-60.9644, -61.9879) -> (-55.9644, -58.9879)
  line L56 (-10.9644, -61.9879) -> (-60.9644, -61.9879)
  line L57 (-11.9644, -52.9879) -> (-19.9644, -52.9879)
  line L58 (-11.9644, -60.9879) -> (-11.9644, -52.9879)
  line L59 (-19.9644, -60.9879) -> (-11.9644, -60.9879)
  line L60 (-19.9644, -52.9879) -> (-19.9644, -60.9879)
  line L61 (-14.9644, -52.9879) -> (-12.9644, -52.9879)
  line L62 (-14.9644, -42.9879) -> (-14.9644, -52.9879)
  line L63 (-12.9644, -42.9879) -> (-14.9644, -42.9879)
  line L64 (-12.9644, -52.9879) -> (-12.9644, -42.9879)
  line L65 (-29.9644, -59.9879) -> (-19.9644, -59.9879)
  line L66 (-29.9644, -57.9879) -> (-29.9644, -59.9879)
  line L67 (-19.9644, -57.9879) -> (-29.9644, -57.9879)
  line L68 (-19.9644, -59.9879) -> (-19.9644, -57.9879)
  circle C1 centre (-24.4644, 61.5121) radius 1.7
  circle C2 centre (-123.9644, 54.5121) radius 1.7
  circle C3 centre (-117.4644, -55.4879) radius 1.7
  circle C4 centre (-17.4644, -48.4879) radius 1.7
  circle C5 centre (-24.4644, -55.4879) radius 1.7
  circle C6 centre (-123.9644, -48.4879) radius 1.7
  circle C7 centre (-117.4644, 61.5121) radius 1.7
  circle C8 centre (-17.4644, 54.5121) radius 1.7
  circle C9 centre (-17.4644, -48.4879) radius 1.7
  circle C10 centre (-24.4644, -55.4879) radius 1.7
  circle C11 centre (-17.4644, -48.4879) radius 3.15
  circle C12 centre (-24.4644, -55.4879) radius 3.15
  point P70 (-12.9644, -52.9879)
  point P74 (-19.9644, -59.9879)
  point P71 (-14.9644, -52.9879)
  point P73 (-12.9644, -42.9879)
  point P75 (-29.9644, -59.9879)
  point P77 (-19.9644, -57.9879)
  horizontal L61
  vertical L62
  horizontal L63
  vertical L64
  coincident L57 P70
  horizontal L65
  vertical L66
  horizontal L67
  vertical L68
  coincident L60 P74
  concentric C9 C11
  concentric C10 C12
  dimension "column_support_width_1" distance P70 P71 = 2
  dimension "column_support_height_1" distance P70 P73 = 10
  dimension "d79_1" distance P74 P75 = 10 (= "column_support_height_1")
  dimension "d80_1" distance P74 P77 = 2 (= "column_support_width_1")
  dimension "M3_head_d_1" diameter C11 = 6.3
  dimension "d85_1" diameter C12 = 6.3 (= "M3_head_d_1")
extrude "Extrude5" add sketch "supports bottom" profile of L53 L57 L60 L61 L62 L63 L64 L65 L66 L67 L68 C11 C12 along normal blind 10 (= "column_support_height_1") named "d86_1"
chamfer "Chamfer2" distance 10 (= "column_support_height_1") named "d88_1"
sketch "left side holes" plane through (0, 0, 75) normal (0, 0, 1) x axis (-1, 0, 0)
  line L1 (-11.9644, -60.9879) -> (-19.9644, -60.9879)
  line L2 (-11.9644, -52.9879) -> (-11.9644, -60.9879)
  line L3 (-19.9644, -52.9879) -> (-11.9644, -52.9879)
  line L4 (-19.9644, -60.9879) -> (-19.9644, -52.9879)
  line L5 (-19.9644, -57.9879) -> (-29.9644, -57.9879)
  line L6 (-19.9644, -59.9879) -> (-19.9644, -57.9879)
  line L7 (-29.9644, -59.9879) -> (-19.9644, -59.9879)
  line L8 (-29.9644, -57.9879) -> (-29.9644, -59.9879)
  line L9 (-14.9644, -42.9879) -> (-14.9644, -52.9879)
  line L10 (-12.9644, -42.9879) -> (-14.9644, -42.9879)
  line L11 (-14.9644, -52.9879) -> (-12.9644, -52.9879)
  line L12 (-12.9644, -52.9879) -> (-12.9644, -42.9879)
  line L13 (-18.9144, -59.9379) -> (-13.0144, -59.9379)
  line L14 (-18.9144, -54.0379) -> (-18.9144, -59.9379)
  line L15 (-13.0144, -54.0379) -> (-18.9144, -54.0379)
  line L16 (-13.0144, -59.9379) -> (-13.0144, -54.0379)
  line L17 (-18.9644, -59.9879) -> (-12.9644, -59.9879)
  line L18 (-18.9644, -53.9879) -> (-18.9644, -59.9879)
  line L19 (-12.9644, -53.9879) -> (-18.9644, -53.9879)
  line L20 (-12.9644, -59.9879) -> (-12.9644, -53.9879)
  circle C1 centre (-15.9644, -56.9879) radius 1.7
  dimension "M3_d_1" diameter C1 = 3.4
extrude "Extrude6" add sketch "left side holes" profile of L3 L4 L5 L6 L7 L8 L9 L10 L11 L12 against normal blind 10 named "d90_1" (magnitude of "-column_support_height_1")
chamfer "Chamfer3" distance 10 (= "column_support_height_1") named "d92_1"
hole "Hole1" HoleDepth 10 (= "column_support_height_1") named "d93_1" HoleDiameter 3.4 named "d94_1" TipAngle 118 named "d95_1"
sketch "Sketch4" plane through (0, 60.9879, 0) normal (0, 1, 0) x axis (-1, 0, 0)
  line L1 (-11.9644, 5) -> (-19.9644, 5)
  line L2 (-11.9644, 75) -> (-11.9644, 5)
  line L3 (-19.9644, 75) -> (-11.9644, 75)
  line L4 (-19.9644, 5) -> (-19.9644, 75)
  line L5 (-23.511, 60) -> (-11.9644, 60)
  line L6 (-25, 20) -> (-11.9644, 20)
  circle C1 centre (-15.9644, 60) radius 1.7
  circle C2 centre (-15.9644, 20) radius 1.7
  point P7 (-11.9644, 60)
  point P8 (-11.9644, 60)
  point P6 (-11.9644, 20)
  point P10 (-11.9644, 20)
  point P12 (-15.9644, 60)
  point P13 (-15.9644, 20)
  coincident P7 P8
  perpendicular L4 L5
  coincident P6 P10
  perpendicular L2 L6
  coincident L5 P12
  coincident L6 P13
  dimension "d103_1" diameter C1 = 3.4 (= "M3_d_1")
  dimension "d104_1" diameter C2 = 3.4 (= "M3_d_1")
  dimension "d105_1" distance L2 P12 = 4 (= "support_column_side / 2")
  dimension "d106_1" distance L2 P13 = 4 (= "support_column_side / 2")
hole "Hole3" HoleDepth 5.76 (= "support_column_side * 0.72") named "d110_1" HoleDiameter 3.4 named "d111_1" TipAngle 180 named "d112_1"
extrude "Extrude7" add sketch "left side holes" profile of C1 L13 L14 L15 L16 along normal blind 1.45 (= "( top_cover_thickness / 2 ) - wall_clearance") named "d236_1"
position "Position6"
work_plane "WorkPlane3" AlongDistance 1 (= "plate_square_thick - side_wall_col_length + wall_clearance")
sketch "Sketch5" plane through (11.9644, 0, 0) normal (-1, 0, 0) x axis (0, -1, 0)
  line L1 (-52.9879, 5) -> (-60.9879, 5)
  line L2 (-52.9879, 75) -> (-52.9879, 5)
  line L3 (-60.9879, 75) -> (-52.9879, 75)
  line L4 (-60.9879, 5) -> (-60.9879, 75)
  line L5 (-56.5129, 75) -> (-60.9879, 75)
  line L6 (-56.5129, 65) -> (-56.5129, 75)
  line L7 (-60.9879, 65) -> (-56.5129, 65)
  line L8 (-60.9879, 75) -> (-60.9879, 65)
  line L9 (-56.4129, 5) -> (-60.9879, 5)
  line L10 (-56.4129, 15) -> (-56.4129, 5)
  line L11 (-60.9879, 15) -> (-56.4129, 15)
  line L12 (-60.9879, 5) -> (-60.9879, 15)
  point P5 (-60.9879, 75)
  point P6 (-60.9879, 75)
  point P2 (-60.9879, 5)
  point P10 (-60.9879, 5)
  point P7 (-56.5129, 75)
  point P11 (-56.4129, 5)
  point P13 (-60.9879, 15)
  horizontal L5
  vertical L6
  horizontal L7
  vertical L8
  coincident P5 P6
  horizontal L9
  vertical L10
  horizontal L11
  vertical L12
  coincident P2 P10
  dimension "d271" distance P6 P7 = 4.475 (= "side_wall_col_length / 2 - wall_clearance")
  dimension "d272" distance L5 L7 = 10 (= "column_support_height")
  dimension "d273" distance P10 P11 = 4.575 (= "side_wall_col_length / 2 + wall_clearance")
  dimension "d274" distance P10 P13 = 10 (= "column_support_height")
extrude "Extrude8" add sketch "Sketch5" profile of L1 L3 L4 L5 L6 L7 L8 L9 L10 L11 L12 along normal blind 2 (= "2 * ( plate_square_thick - side_wall_col_length + wall_clearance )")
mirror "Mirror1" mirrorStitchTolerance 0.1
